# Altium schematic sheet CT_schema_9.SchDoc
size 387 x 278 mm
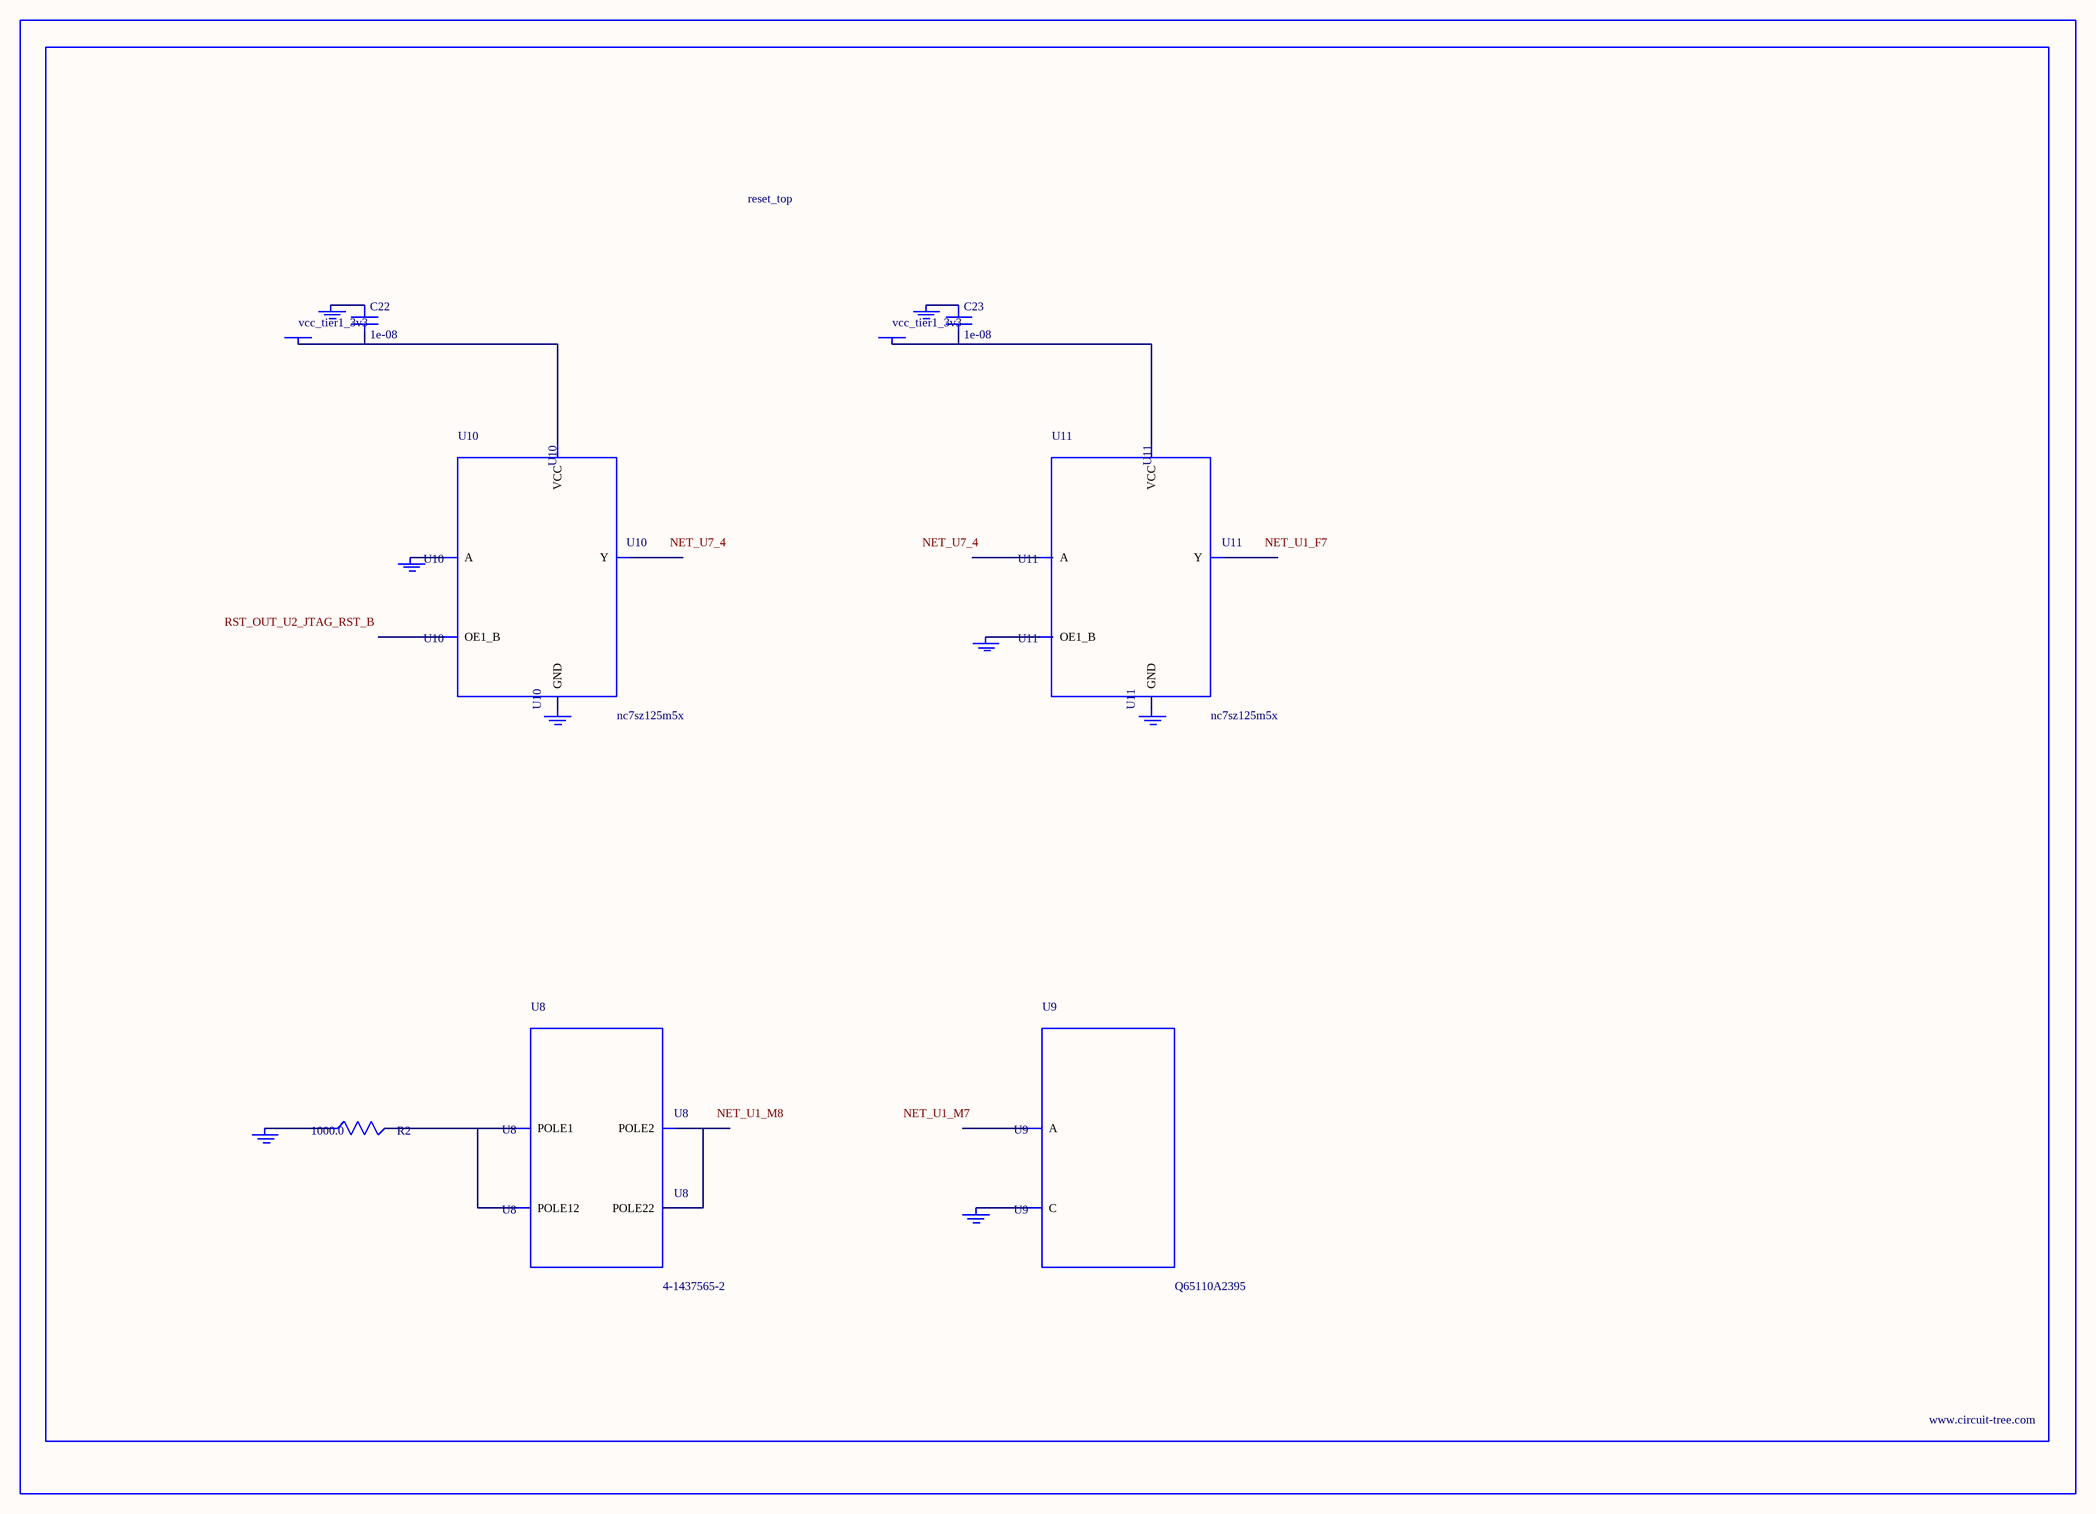
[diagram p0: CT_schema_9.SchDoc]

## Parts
BORDER8  (no value)
C22  1e-08  [C0402]
C23  1e-08  [C0402]
GND_INSTANCE_8_0  (no value)
GND_INSTANCE_8_1  (no value)
GND_INSTANCE_8_2  (no value)
GND_INSTANCE_8_3  (no value)
GND_INSTANCE_8_4  (no value)
GND_INSTANCE_8_5  (no value)
GND_INSTANCE_8_6  (no value)
GND_INSTANCE_8_7  (no value)
POWER_INSTANCE_8_0  vcc_tier1_3v3
POWER_INSTANCE_8_1  vcc_tier1_3v3
R2  1000.0  [R0603]
U8  4-1437565-2  [SW_4-1437565-2]
U9  Q65110A2395  [LGM67K-G1J2-24-Z]
U10  nc7sz125m5x  [NC7SZ125M5X]
U11  nc7sz125m5x  [NC7SZ125M5X]

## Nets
NetC22_1: C22.1 GND_INSTANCE_8_2.0(GND)
NetC22_2: C22.2 POWER_INSTANCE_8_0.0(PWR) U10.5(VCC)
NetC23_1: C23.1 GND_INSTANCE_8_5.0(GND)
NetC23_2: C23.2 POWER_INSTANCE_8_1.0(PWR) U11.5(VCC)
NetGND_INSTANCE_8_0_0: GND_INSTANCE_8_0.0(GND) R2.1
NetGND_INSTANCE_8_1_0: GND_INSTANCE_8_1.0(GND) U9.C
NetGND_INSTANCE_8_3_0: GND_INSTANCE_8_3.0(GND) U10.2(A)
NetGND_INSTANCE_8_4_0: GND_INSTANCE_8_4.0(GND) U10.3(GND)
NetGND_INSTANCE_8_6_0: GND_INSTANCE_8_6.0(GND) U11.1(OE1_B)
NetGND_INSTANCE_8_7_0: GND_INSTANCE_8_7.0(GND) U11.3(GND)
NetR2_2: R2.2 U8.1(POLE1) U8.2(POLE12)
NetU8_3: U8.3(POLE2) U8.4(POLE22)

Not connected (* = marked no-connect by the designer): U9 A; U10 1(OE1_B) 4(Y); U11 2(A) 4(Y)

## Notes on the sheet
- Labels drawn without touching a wire or pin: NET_U1_F7, NET_U1_M7, NET_U1_M8, NET_U7_4, RST_OUT_U2_JTAG_RST_B

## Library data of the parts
BORDER8 = BORDER_PAGE8
C22 C23 = C0402C103K3RAC
GND_INSTANCE_8_0-GND_INSTANCE_8_7 = GND
POWER_INSTANCE_8_0 POWER_INSTANCE_8_1 = PWR
R2 = RC0603JR-071KL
